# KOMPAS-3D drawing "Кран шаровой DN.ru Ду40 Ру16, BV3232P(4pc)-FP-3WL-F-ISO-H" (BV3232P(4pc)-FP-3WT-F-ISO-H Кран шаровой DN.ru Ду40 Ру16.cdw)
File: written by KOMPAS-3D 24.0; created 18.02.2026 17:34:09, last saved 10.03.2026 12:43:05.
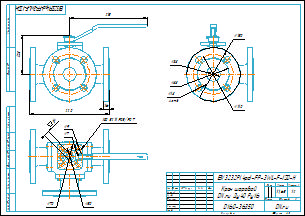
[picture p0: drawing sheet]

Document properties: Автор: R2D2; Форматы листов документа: A3; Полное имя файла: ..\..\BV3232P(4pc)-FP-3WL-F-ISO-H Кран шаровой DN.ru Ду15-100 Ру16\DN40\BV3232P(4pc)-FP-3WL-F-ISO-H Кран шаровой DN.ru Ду40 Ру16.m3d; Масса: 11.65; Наименование: Кран шаровой DN.ru Ду40 Ру16; Количество листов документа: 1; Примечание: D160-36359

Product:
- Part/product: Кран шаровой DN.ru Ду40 Ру16  | designation BV3232P(4pc)-FP-3WL-F-ISO-H
    Масса: 11.65
    Раздел спецификации: Прочие изделия
    Примечание: D160-36359

Views: Вид 1, Спереди, Проекционный вид 2
Referenced files in E:\Работа\Зайцев\BV3232P(4pc)-FP-3WL-F-ISO-H Кран шаровой DN.ru Ду15-100 Ру16\DN40\: BV3232P(4pc)-FP-3WL-F-ISO-H Кран шаровой DN.ru Ду40 Ру16.m3d
Referenced files in E:\Работа\Зайцев\Для компаса\: чертеж DN.ru А3.cdt
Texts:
  BV3232P(4pc)-FP-3WL-F-ISO-H
  чертеж DN.ru А3.cdt
  Кран шаровой
  DN.ru Ду40 Ру16
  Кран шаровой DN.ru Ду40 Ру16
  BV3232P(4pc)-FP-3WL-F-ISO-H Кран шаровой DN.ru Ду40 Ру16
Dimensions and other numbers on the sheet: 0; 3; 2; 4; 220; 16; 108; 215; 150; 110; 88; 18; 4 отв.; 38; 1:2; 1; 11,65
